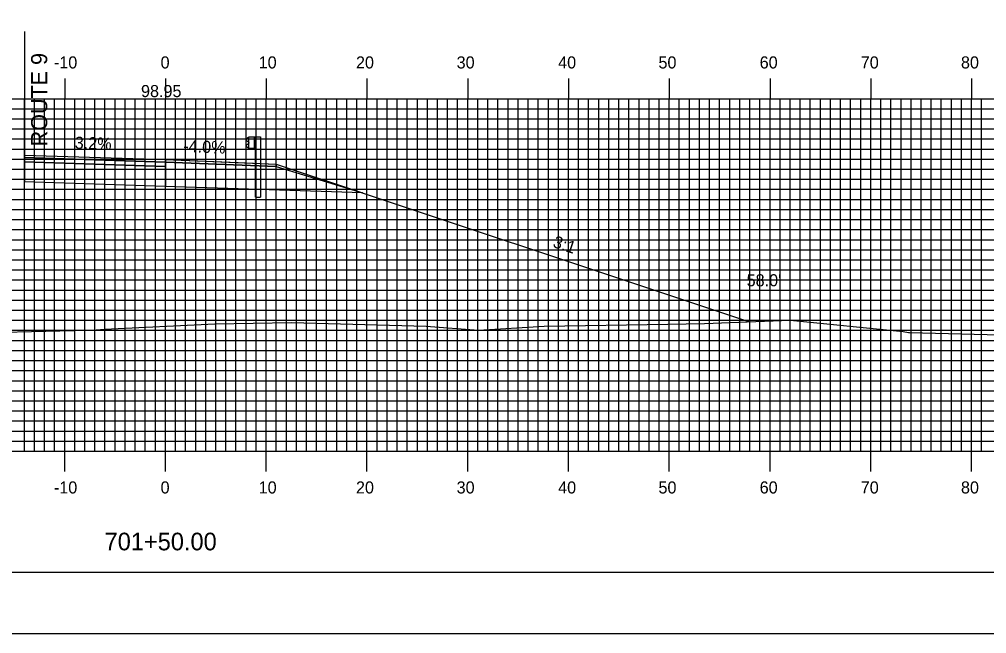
# Model space of a CAD drawing. Extents: x 852936 to 853279, y 364366 to 364586.
# Drawn here: x 853087.2 to 853183.2, y 364365.7 to 364426.7 of the extents above; entities that cross this region are included whole.
import ezdxf

# ---------------------------------------------------------------- set-up
doc = ezdxf.new("R2010")
doc.units = 0
for name, color, linetype in [('ANNOTATION', 7, 'Continuous'), ('BORDER', 7, 'Continuous'), ('D_Guardrail_Beam_Rt', 7, 'Continuous'), ('D_Roadway_Centerline_Text', 7, 'Continuous'), ('D_Roadway_Edge_Shoulder', 7, 'Continuous'), ('D_Roadway_Edge_TW', 7, 'Continuous'), ('D_Roadway_Pavement', 7, 'Continuous'), ('D_Roadway_SlopeLines', 7, 'Continuous'), ('D_Roadway_SubGrade', 7, 'Continuous'), ('D_Text_Standard', 7, 'Continuous'), ('H_V ANNOTATION', 7, 'Continuous'), ('MAJOR', 7, 'Continuous'), ('MINOR', 7, 'Continuous'), ('PLOT BOUNDARY', 7, 'Continuous'), ('S_Roadway_Centerline', 7, 'Continuous')]:
    doc.layers.add(name, color=color, linetype=linetype)

msp = doc.modelspace()

# ---------------------------------------------------------------- linework, layer by layer
at = {"layer": 'BORDER'}
msp.add_lwpolyline([(852952.091, 364371.787), (853272.091, 364371.787), (853272.091, 364581.787), (852952.091, 364581.787)], close=True, dxfattribs=at)
at = {"layer": 'D_Guardrail_Beam_Rt'}
for p, q in [((853109.872, 364414.891), (853109.729, 364414.791)), ((853109.729, 364414.648), (853109.924, 364414.512)), ((853109.924, 364414.313), (853109.729, 364414.177)), ((853109.962, 364414.912), (853109.888, 364414.898)), ((853109.958, 364414.448), (853109.958, 364414.377)), ((853109.962, 364414.996), (853110.65, 364414.996)), ((853109.962, 364413.829), (853109.962, 364414.996)), ((853110.483, 364414.996), (853110.483, 364413.829)), ((853110.587, 364414.996), (853110.587, 364413.829)), ((853110.65, 364414.996), (853111.121, 364414.996)), ((853110.65, 364414.996), (853110.65, 364413.829)), ((853111.121, 364414.996), (853111.121, 364408.996)), ((853109.729, 364414.034), (853109.872, 364413.934)), ((853109.888, 364413.927), (853109.962, 364413.912)), ((853110.65, 364413.829), (853109.962, 364413.829)), ((853110.629, 364408.996), (853110.629, 364413.829)), ((853110.629, 364408.996), (853111.121, 364408.996))]:
    msp.add_line(p, q, dxfattribs=at)
for centre, major_axis, start_param, end_param in [((853109.779, 364414.72), (-0.0877, 0), 5.323254, 7.243116), ((853109.779, 364414.105), (-0.0877, 0), 5.323254, 7.243116), ((853109.896, 364414.857), (-0.0417, 0), 4.907132, 5.323254), ((853109.879, 364414.448), (0.0789, 0), 0, 0.959931), ((853109.879, 364414.377), (0.0789, 0), 5.323254, 6.283185), ((853109.896, 364413.968), (-0.0417, 0), 0.959931, 1.376053)]:
    msp.add_ellipse(centre, major_axis=major_axis, ratio=0.995501, start_param=start_param, end_param=end_param, dxfattribs=at)
at = {"layer": 'D_Roadway_Edge_Shoulder'}
for points in [[(853101.691, 364412.732), (853112.691, 364412.292), (853112.691, 364412.042), (853101.691, 364412.482)], [(853101.691, 364412.732), (853109.691, 364412.412), (853109.691, 364412.412), (853112.691, 364412.292), (853112.691, 364412.042), (853101.691, 364412.482)], [(853101.691, 364412.732), (853109.691, 364412.412), (853109.691, 364412.412), (853112.691, 364412.292), (853112.691, 364412.042), (853101.691, 364412.482)], [(853101.691, 364412.732), (853112.691, 364412.292), (853112.691, 364412.042), (853101.691, 364412.482)], [(853101.691, 364412.732), (853112.691, 364412.292), (853112.691, 364412.042), (853101.691, 364412.482)]]:
    msp.add_lwpolyline(points, close=True, dxfattribs=at)
at = {"layer": 'D_Roadway_Edge_TW'}
msp.add_lwpolyline([(853087.695, 364413.182), (853101.691, 364412.732), (853101.691, 364412.482), (853087.695, 364412.932)], close=True, dxfattribs=at)
msp.add_lwpolyline([(853087.695, 364413.182), (853101.691, 364412.732), (853101.691, 364412.482), (853087.695, 364412.932)], close=True, dxfattribs=at)
msp.add_lwpolyline([(853087.695, 364413.182), (853101.691, 364412.732), (853101.691, 364412.482), (853087.695, 364412.932)], close=True, dxfattribs=at)
msp.add_lwpolyline([(853087.695, 364413.182), (853101.691, 364412.732), (853101.691, 364412.482), (853087.695, 364412.932)], close=True, dxfattribs=at)
at = {"layer": 'D_Roadway_Pavement'}
msp.add_lwpolyline([(853087.695, 364412.932), (853101.691, 364412.482), (853101.691, 364412.066), (853087.695, 364412.516)], close=True, dxfattribs=at)
msp.add_lwpolyline([(853087.695, 364412.932), (853101.691, 364412.482), (853101.691, 364412.066), (853087.695, 364412.516)], close=True, dxfattribs=at)
msp.add_lwpolyline([(853087.695, 364412.932), (853101.691, 364412.482), (853101.691, 364412.066), (853087.695, 364412.516)], close=True, dxfattribs=at)
msp.add_lwpolyline([(853087.695, 364412.932), (853101.691, 364412.482), (853101.691, 364412.066), (853087.695, 364412.516)], close=True, dxfattribs=at)
msp.add_lwpolyline([(853101.691, 364412.482), (853101.691, 364412.066)], dxfattribs=at)
msp.add_lwpolyline([(853101.691, 364412.482), (853101.691, 364412.066)], dxfattribs=at)
msp.add_lwpolyline([(853101.691, 364412.482), (853101.691, 364412.066)], dxfattribs=at)
msp.add_lwpolyline([(853101.691, 364412.482), (853101.691, 364412.066)], dxfattribs=at)
msp.add_lwpolyline([(853101.691, 364412.482), (853101.691, 364412.066)], dxfattribs=at)
msp.add_lwpolyline([(853101.691, 364412.482), (853101.691, 364412.066)], dxfattribs=at)
msp.add_lwpolyline([(853101.691, 364412.482), (853101.691, 364412.066)], dxfattribs=at)
msp.add_lwpolyline([(853101.691, 364412.482), (853101.691, 364412.066)], dxfattribs=at)
msp.add_lwpolyline([(853101.691, 364412.482), (853101.691, 364412.066)], dxfattribs=at)
msp.add_lwpolyline([(853101.691, 364412.482), (853101.691, 364412.066)], dxfattribs=at)
msp.add_lwpolyline([(853101.691, 364412.482), (853101.691, 364412.066)], dxfattribs=at)
msp.add_lwpolyline([(853101.691, 364412.482), (853101.691, 364412.066)], dxfattribs=at)
msp.add_lwpolyline([(853101.691, 364412.482), (853101.691, 364412.066)], dxfattribs=at)
msp.add_lwpolyline([(853101.691, 364412.482), (853101.691, 364412.066)], dxfattribs=at)
at = {"layer": 'D_Roadway_SlopeLines'}
msp.add_lwpolyline([(853112.691, 364412.292), (853159.65, 364396.64)], dxfattribs=at)
msp.add_lwpolyline([(853112.691, 364412.292), (853159.65, 364396.64)], dxfattribs=at)
msp.add_lwpolyline([(853112.691, 364412.292), (853159.65, 364396.64)], dxfattribs=at)
msp.add_lwpolyline([(853112.691, 364412.292), (853159.65, 364396.64)], dxfattribs=at)
at = {"layer": 'D_Roadway_SubGrade'}
msp.add_line((853087.695, 364425.473), (853087.695, 364410.516), dxfattribs=at)
for points in [[(853087.695, 364412.516), (853101.691, 364412.066), (853101.691, 364410.066), (853087.695, 364410.516)], [(853087.695, 364412.516), (853101.691, 364412.066), (853101.691, 364410.066), (853087.695, 364410.516)], [(853087.695, 364412.516), (853101.691, 364412.066), (853101.691, 364410.066), (853087.695, 364410.516)], [(853087.695, 364412.516), (853101.691, 364412.066), (853101.691, 364410.066), (853087.695, 364410.516)], [(853101.691, 364412.066), (853101.691, 364412.482), (853112.691, 364412.042), (853112.691, 364412.292), (853121.263, 364409.435), (853101.691, 364410.066)], [(853101.691, 364412.066), (853101.691, 364412.482), (853112.691, 364412.042), (853112.691, 364412.292), (853121.263, 364409.435), (853101.691, 364410.066)], [(853101.691, 364412.066), (853101.691, 364412.482), (853112.691, 364412.042), (853112.691, 364412.292), (853121.263, 364409.435), (853101.691, 364410.066)], [(853101.691, 364412.066), (853101.691, 364412.482), (853112.691, 364412.042), (853121.263, 364409.435), (853101.691, 364410.066)], [(853101.691, 364412.066), (853101.691, 364412.482), (853112.691, 364412.042), (853112.691, 364412.292), (853121.263, 364409.435), (853101.691, 364410.066)]]:
    msp.add_lwpolyline(points, close=True, dxfattribs=at)
at = {"layer": 'MAJOR'}
for p, q in [((853091.691, 364420.791), (853091.691, 364418.787)), ((853101.691, 364420.791), (853101.691, 364418.787)), ((853111.691, 364420.791), (853111.691, 364418.787)), ((853121.691, 364420.791), (853121.691, 364418.787)), ((853131.691, 364420.791), (853131.691, 364418.787)), ((853141.691, 364420.791), (853141.691, 364418.787)), ((853151.691, 364420.791), (853151.691, 364418.787)), ((853161.691, 364420.791), (853161.691, 364418.787)), ((853171.691, 364420.791), (853171.691, 364418.787)), ((853181.691, 364420.791), (853181.691, 364418.787)), ((852961.691, 364418.787), (853241.691, 364418.787)), ((852961.691, 364418.787), (853241.691, 364418.787)), ((853091.691, 364383.787), (853091.691, 364418.787)), ((853101.691, 364383.787), (853101.691, 364418.787)), ((853111.691, 364383.787), (853111.691, 364418.787)), ((853121.691, 364383.787), (853121.691, 364418.787)), ((853131.691, 364383.787), (853131.691, 364418.787)), ((853141.691, 364383.787), (853141.691, 364418.787)), ((853151.691, 364383.787), (853151.691, 364418.787)), ((853161.691, 364383.787), (853161.691, 364418.787)), ((853171.691, 364383.787), (853171.691, 364418.787)), ((853181.691, 364383.787), (853181.691, 364418.787)), ((852961.691, 364413.787), (853241.691, 364413.787)), ((852961.691, 364408.787), (853241.691, 364408.787)), ((852961.691, 364403.787), (853241.691, 364403.787)), ((852961.691, 364398.787), (853241.691, 364398.787)), ((852961.691, 364393.787), (853241.691, 364393.787)), ((852961.691, 364388.787), (853241.691, 364388.787)), ((852961.691, 364383.787), (853241.691, 364383.787)), ((852961.691, 364383.787), (853241.691, 364383.787)), ((853091.691, 364381.783), (853091.691, 364383.787)), ((853101.691, 364381.783), (853101.691, 364383.787)), ((853111.691, 364381.783), (853111.691, 364383.787)), ((853121.691, 364381.783), (853121.691, 364383.787)), ((853131.691, 364381.783), (853131.691, 364383.787)), ((853141.691, 364381.783), (853141.691, 364383.787)), ((853151.691, 364381.783), (853151.691, 364383.787)), ((853161.691, 364381.783), (853161.691, 364383.787)), ((853171.691, 364381.783), (853171.691, 364383.787)), ((853181.691, 364381.783), (853181.691, 364383.787))]:
    msp.add_line(p, q, dxfattribs=at)
at = {"layer": 'MINOR'}
for p, q in [((853087.691, 364383.787), (853087.691, 364418.787)), ((853088.691, 364383.787), (853088.691, 364418.787)), ((853089.691, 364383.787), (853089.691, 364418.787)), ((853090.691, 364383.787), (853090.691, 364418.787)), ((853092.691, 364383.787), (853092.691, 364418.787)), ((853093.691, 364383.787), (853093.691, 364418.787)), ((853094.691, 364383.787), (853094.691, 364418.787)), ((853095.691, 364383.787), (853095.691, 364418.787)), ((853096.691, 364383.787), (853096.691, 364418.787)), ((853097.691, 364383.787), (853097.691, 364418.787)), ((853098.691, 364383.787), (853098.691, 364418.787)), ((853099.691, 364383.787), (853099.691, 364418.787)), ((853100.691, 364383.787), (853100.691, 364418.787)), ((853102.691, 364383.787), (853102.691, 364418.787)), ((853103.691, 364383.787), (853103.691, 364418.787)), ((853104.691, 364383.787), (853104.691, 364418.787)), ((853105.691, 364383.787), (853105.691, 364418.787)), ((853106.691, 364383.787), (853106.691, 364418.787)), ((853107.691, 364383.787), (853107.691, 364418.787)), ((853108.691, 364383.787), (853108.691, 364418.787)), ((853109.691, 364383.787), (853109.691, 364418.787)), ((853110.691, 364383.787), (853110.691, 364418.787)), ((853112.691, 364383.787), (853112.691, 364418.787)), ((853113.691, 364383.787), (853113.691, 364418.787)), ((853114.691, 364383.787), (853114.691, 364418.787)), ((853115.691, 364383.787), (853115.691, 364418.787)), ((853116.691, 364383.787), (853116.691, 364418.787)), ((853117.691, 364383.787), (853117.691, 364418.787)), ((853118.691, 364383.787), (853118.691, 364418.787)), ((853119.691, 364383.787), (853119.691, 364418.787)), ((853120.691, 364383.787), (853120.691, 364418.787)), ((853122.691, 364383.787), (853122.691, 364418.787)), ((853123.691, 364383.787), (853123.691, 364418.787)), ((853124.691, 364383.787), (853124.691, 364418.787)), ((853125.691, 364383.787), (853125.691, 364418.787)), ((853126.691, 364383.787), (853126.691, 364418.787)), ((853127.691, 364383.787), (853127.691, 364418.787)), ((853128.691, 364383.787), (853128.691, 364418.787)), ((853129.691, 364383.787), (853129.691, 364418.787)), ((853130.691, 364383.787), (853130.691, 364418.787)), ((853132.691, 364383.787), (853132.691, 364418.787)), ((853133.691, 364383.787), (853133.691, 364418.787)), ((853134.691, 364383.787), (853134.691, 364418.787)), ((853135.691, 364383.787), (853135.691, 364418.787)), ((853136.691, 364383.787), (853136.691, 364418.787)), ((853137.691, 364383.787), (853137.691, 364418.787)), ((853138.691, 364383.787), (853138.691, 364418.787)), ((853139.691, 364383.787), (853139.691, 364418.787)), ((853140.691, 364383.787), (853140.691, 364418.787)), ((853142.691, 364383.787), (853142.691, 364418.787)), ((853143.691, 364383.787), (853143.691, 364418.787)), ((853144.691, 364383.787), (853144.691, 364418.787)), ((853145.691, 364383.787), (853145.691, 364418.787)), ((853146.691, 364383.787), (853146.691, 364418.787)), ((853147.691, 364383.787), (853147.691, 364418.787)), ((853148.691, 364383.787), (853148.691, 364418.787)), ((853149.691, 364383.787), (853149.691, 364418.787)), ((853150.691, 364383.787), (853150.691, 364418.787)), ((853152.691, 364383.787), (853152.691, 364418.787)), ((853153.691, 364383.787), (853153.691, 364418.787)), ((853154.691, 364383.787), (853154.691, 364418.787)), ((853155.691, 364383.787), (853155.691, 364418.787)), ((853156.691, 364383.787), (853156.691, 364418.787)), ((853157.691, 364383.787), (853157.691, 364418.787)), ((853158.691, 364383.787), (853158.691, 364418.787)), ((853159.691, 364383.787), (853159.691, 364418.787)), ((853160.691, 364383.787), (853160.691, 364418.787)), ((853162.691, 364383.787), (853162.691, 364418.787)), ((853163.691, 364383.787), (853163.691, 364418.787)), ((853164.691, 364383.787), (853164.691, 364418.787)), ((853165.691, 364383.787), (853165.691, 364418.787)), ((853166.691, 364383.787), (853166.691, 364418.787)), ((853167.691, 364383.787), (853167.691, 364418.787)), ((853168.691, 364383.787), (853168.691, 364418.787)), ((853169.691, 364383.787), (853169.691, 364418.787)), ((853170.691, 364383.787), (853170.691, 364418.787)), ((853172.691, 364383.787), (853172.691, 364418.787)), ((853173.691, 364383.787), (853173.691, 364418.787)), ((853174.691, 364383.787), (853174.691, 364418.787)), ((853175.691, 364383.787), (853175.691, 364418.787)), ((853176.691, 364383.787), (853176.691, 364418.787)), ((853177.691, 364383.787), (853177.691, 364418.787)), ((853178.691, 364383.787), (853178.691, 364418.787)), ((853179.691, 364383.787), (853179.691, 364418.787)), ((853180.691, 364383.787), (853180.691, 364418.787)), ((853182.691, 364383.787), (853182.691, 364418.787)), ((852961.691, 364417.787), (853241.691, 364417.787)), ((852961.691, 364416.787), (853241.691, 364416.787)), ((852961.691, 364415.787), (853241.691, 364415.787)), ((852961.691, 364414.787), (853241.691, 364414.787)), ((852961.691, 364412.787), (853241.691, 364412.787)), ((852961.691, 364411.787), (853241.691, 364411.787)), ((852961.691, 364410.787), (853241.691, 364410.787)), ((852961.691, 364409.787), (853241.691, 364409.787)), ((852961.691, 364407.787), (853241.691, 364407.787)), ((852961.691, 364406.787), (853241.691, 364406.787)), ((852961.691, 364405.787), (853241.691, 364405.787)), ((852961.691, 364404.787), (853241.691, 364404.787)), ((852961.691, 364402.787), (853241.691, 364402.787)), ((852961.691, 364401.787), (853241.691, 364401.787)), ((852961.691, 364400.787), (853241.691, 364400.787)), ((852961.691, 364399.787), (853241.691, 364399.787)), ((852961.691, 364397.787), (853241.691, 364397.787)), ((852961.691, 364396.787), (853241.691, 364396.787)), ((852961.691, 364395.787), (853241.691, 364395.787)), ((852961.691, 364394.787), (853241.691, 364394.787)), ((852961.691, 364392.787), (853241.691, 364392.787)), ((852961.691, 364391.787), (853241.691, 364391.787)), ((852961.691, 364390.787), (853241.691, 364390.787)), ((852961.691, 364389.787), (853241.691, 364389.787)), ((852961.691, 364387.787), (853241.691, 364387.787)), ((852961.691, 364386.787), (853241.691, 364386.787)), ((852961.691, 364385.787), (853241.691, 364385.787)), ((852961.691, 364384.787), (853241.691, 364384.787))]:
    msp.add_line(p, q, dxfattribs=at)
at = {"layer": 'PLOT BOUNDARY'}
msp.add_lwpolyline([(852935.905, 364365.669), (853275.905, 364365.669), (853275.905, 364585.669), (852935.905, 364585.669)], close=True, dxfattribs=at)
at = {"layer": 'S_Roadway_Centerline'}
msp.add_lwpolyline([(853081.309, 364395.491), (853092.62, 364395.779), (853094.813, 364395.842), (853095.645, 364395.913), (853106.584, 364396.422), (853114.191, 364396.571), (853127.567, 364396.206), (853132.75, 364395.817), (853139.29, 364396.212), (853151.558, 364396.409), (853155.199, 364396.48), (853163.703, 364396.785), (853174.916, 364395.655), (853175.434, 364395.573), (853175.548, 364395.571), (853175.55, 364395.578), (853187.114, 364395.264)], dxfattribs=at)

# ---------------------------------------------------------------- texts
at = {"layer": 'ANNOTATION'}
for s, height, rotation, p in [('ROUTE 9', 1.6, 90, (853089.956, 364414.052)), ('3.2%', 1.2, 358.15838, (853092.677, 364413.823)), ('-4.0%', 1.2, 357.70939, (853103.443, 364413.493)), ('3:1', 1.2, 341.56508, (853140.06, 364404.078))]:
    msp.add_text(s, height=height, rotation=rotation, dxfattribs=at).set_placement(p)
at = {"layer": 'D_Roadway_Centerline_Text'}
msp.add_text('98.95', height=1.2, dxfattribs=at).set_placement((853099.267, 364418.943))
at = {"layer": 'D_Text_Standard'}
msp.add_text("58.0'", height=1.2, dxfattribs=at).set_placement((853159.37, 364400.16))
at = {"layer": 'H_V ANNOTATION'}
for s, height, p in [('-10', 1.2, (853090.621, 364421.787)), ('0', 1.2, (853101.21, 364421.787)), ('10', 1.2, (853110.942, 364421.787)), ('20', 1.2, (853120.599, 364421.787)), ('30', 1.2, (853130.589, 364421.787)), ('40', 1.2, (853140.664, 364421.787)), ('50', 1.2, (853150.621, 364421.787)), ('60', 1.2, (853160.664, 364421.787)), ('70', 1.2, (853170.696, 364421.787)), ('80', 1.2, (853180.642, 364421.787)), ('-10', 1.2, (853090.621, 364379.587)), ('0', 1.2, (853101.21, 364379.587)), ('10', 1.2, (853110.942, 364379.587)), ('20', 1.2, (853120.599, 364379.587)), ('30', 1.2, (853130.589, 364379.587)), ('40', 1.2, (853140.664, 364379.587)), ('50', 1.2, (853150.621, 364379.587)), ('60', 1.2, (853160.664, 364379.587)), ('70', 1.2, (853170.696, 364379.587)), ('80', 1.2, (853180.642, 364379.587)), ('701+50.00', 1.75, (853095.652, 364373.943))]:
    msp.add_text(s, height=height, dxfattribs=at).set_placement(p)

doc.saveas('drawing.dxf')
